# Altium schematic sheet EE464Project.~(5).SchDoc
size A; SheetNumber: 1; SheetTotal: 1
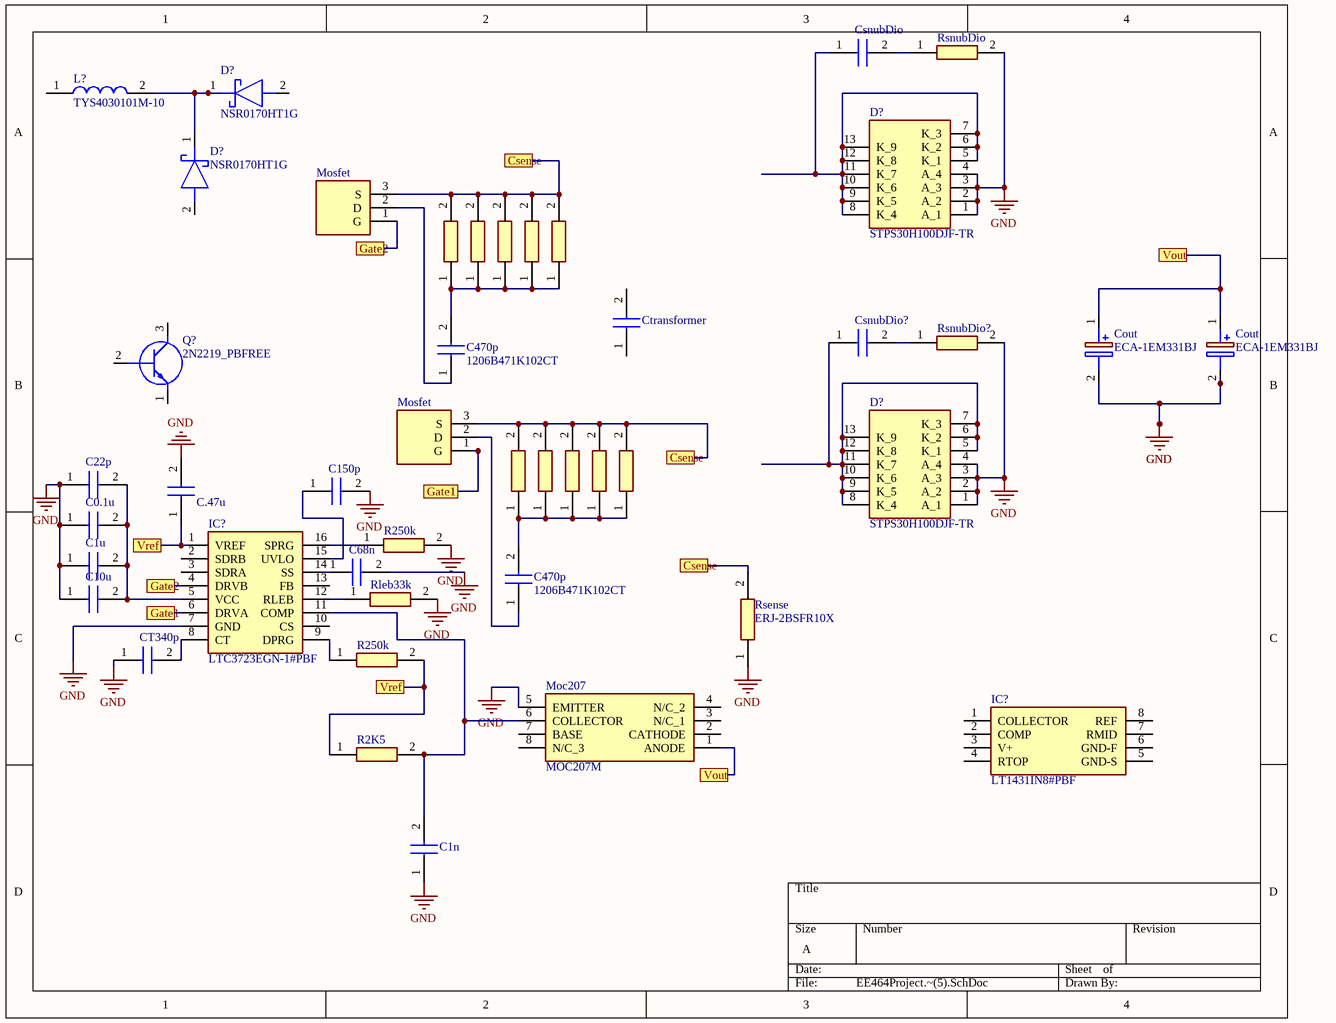
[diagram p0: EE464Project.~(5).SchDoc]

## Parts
(Parts that share a designator on the sheet are numbered #1, #2 ... from top to bottom, then left to right.)
C0.1u  06031C104K4Z2A  [CAPC1608X90N]  (value not drawn)
C1n  04025C102JAT2A  [CAPC1005X56N]  (value not drawn)
C1u  C1608X5R1H105K080AB  [CAPC1608X80N]  (value not drawn)
C10u  CL31A106MBHNNNE  [CAPC3216X180N]  (value not drawn)
C22p  06035A220JAT2A  [CAPC1608X90N]  (value not drawn)
C68n  885012206070  [CAPC1608X87N]  (value not drawn)
C150p  CL10C151JB8NNNC  [CAPC1608X90N]  (value not drawn)
C470p#1  1206B471K102CT  [CAPC3216X180N]
C470p#2  1206B471K102CT  [CAPC3216X180N]
C.47u  CGA4J1X8L1H474K125AE  [CAPC2012X145N]  (value not drawn)
Cout#1  ECA-1EM331BJ  [CAPPRD350W65D825H1250]
Cout#2  ECA-1EM331BJ  [CAPPRD350W65D825H1250]
CsnubDio  GRM1885C2A201JA01D  [CAPC1608X90N]  (value not drawn)
CsnubDio?  GRM1885C2A201JA01D  [CAPC1608X90N]  (value not drawn)
CT340p  GRM1885C2A361JA01D  [CAPC1608X90N]  (value not drawn)
Ctransformer  C1210C104KBRACAUTO  [CAPC3225X280N]  (value not drawn)
D?#1  NSR0170HT1G  [SOD2512X100N]
D?#2  NSR0170HT1G  [SOD2512X100N]
D?#3  STPS30H100DJF-TR  [STPS30H100DJFTR]
D?#4  STPS30H100DJF-TR  [STPS30H100DJFTR]
IC?#1  LTC3723EGN-1#PBF  [SOP64P601X175-16N]
IC?#2  LT1431IN8#PBF  [DIP794W53P254L1016H394Q8N]
L?  TYS4030101M-10  [INDPM4040X300N]
Moc207  MOC207M  [SOIC127P594X363-8N]
Mosfet#1  STW11NK100Z  [TO545P515X1560X2445-3P]  (value not drawn)
Mosfet#2  STW11NK100Z  [TO545P515X1560X2445-3P]  (value not drawn)
Q?  2N2219_PBFREE  [2N3440PBFREE]
R2K5  ERA-3AED2491V  [ERA3AEB101V]  (value not drawn)
R250k#1  MCT06030C2493FP500  [RESC1608X55N]  (value not drawn)
R250k#2  MCT06030C2493FP500  [RESC1608X55N]  (value not drawn)
Rleb33k  ERA-3AED333V  [ERA3AEB101V]  (value not drawn)
Rsense  ERJ-2BSFR10X  [RESC1005X40N]
RsnubDio  RC0603FR-1022RL  [RESC1608X55N]  (value not drawn)
RsnubDio?  RC0603FR-1022RL  [RESC1608X55N]  (value not drawn)
Rsnubmos  CRGH2512F221R  [RESC6432X65N]  (value not drawn)
Rsnubmos?#1  CRGH2512F221R  [RESC6432X65N]  (value not drawn)
Rsnubmos?#2  CRGH2512F221R  [RESC6432X65N]  (value not drawn)
Rsnubmos?#3  CRGH2512F221R  [RESC6432X65N]  (value not drawn)
Rsnubmos?#4  CRGH2512F221R  [RESC6432X65N]  (value not drawn)
Rsnubmos?#5  CRGH2512F221R  [RESC6432X65N]  (value not drawn)
Rsnubmos?#6  CRGH2512F221R  [RESC6432X65N]  (value not drawn)
Rsnubmos?#7  CRGH2512F221R  [RESC6432X65N]  (value not drawn)
Rsnubmos?#8  CRGH2512F221R  [RESC6432X65N]  (value not drawn)
Rsnubmos?#9  CRGH2512F221R  [RESC6432X65N]  (value not drawn)

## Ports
Csense, Gate1, Gate2, Vout, Vref

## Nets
GND: C0.1u.1 C1n.1 C1u.1 C10u.1 C22p.1 C68n.2 C150p.2 C.47u.2 Cout#1.2(-) Cout#2.2(-) CT340p.1 D?#3.1(A_1) D?#3.2(A_2) D?#3.3(A_3) D?#3.4(A_4) D?#4.1(A_1) D?#4.2(A_2) D?#4.3(A_3) D?#4.4(A_4) IC?#1.7(GND) Moc207.5(EMITTER) R250k#1.2 Rleb33k.2 Rsense.1 RsnubDio.2 RsnubDio?.2
Csense: Mosfet#1.3(S) Mosfet#2.3(S) Rsense.2 Rsnubmos.2 Rsnubmos?#1.2 Rsnubmos?#2.2 Rsnubmos?#3.2 Rsnubmos?#4.2 Rsnubmos?#5.2 Rsnubmos?#6.2 Rsnubmos?#7.2 Rsnubmos?#8.2 Rsnubmos?#9.2 ; port Csense
Gate1: IC?#1.6(DRVA) Mosfet#2.1(G) ; port Gate1
Gate2: IC?#1.4(DRVB) Mosfet#1.1(G) ; port Gate2
Vout: Cout#1.1(+) Cout#2.1(+) Moc207.1(ANODE) ; port Vout
Vref: C.47u.1 IC?#1.1(VREF) R2K5.1 R250k#2.2 ; port Vref
NetC0.1u_2: C0.1u.2 C1u.2 C10u.2 C22p.2 IC?#1.5(VCC)
NetC1n_2: C1n.2 IC?#1.11(COMP) Moc207.6(COLLECTOR) R2K5.2
NetC68n_1: C68n.1 IC?#1.14(SS)
NetC150p_1: C150p.1 IC?#1.15(UVLO)
NetC470p#1_1: C470p#1.1 Mosfet#1.2(D)
NetC470p#1_2: C470p#1.2 Rsnubmos?#1.1 Rsnubmos?#2.1 Rsnubmos?#3.1 Rsnubmos?#4.1 Rsnubmos?#5.1
NetC470p#2_1: C470p#2.1 Mosfet#2.2(D)
NetC470p#2_2: C470p#2.2 Rsnubmos.1 Rsnubmos?#6.1 Rsnubmos?#7.1 Rsnubmos?#8.1 Rsnubmos?#9.1
NetCsnubDio?_1: CsnubDio?.1 D?#4.5(K_1) D?#4.6(K_2) D?#4.7(K_3) D?#4.8(K_4) D?#4.9(K_5) D?#4.10(K_6) D?#4.11(K_7) D?#4.12(K_8) D?#4.13(K_9)
NetCsnubDio?_2: CsnubDio?.2 RsnubDio?.1
NetCsnubDio_1: CsnubDio.1 D?#3.5(K_1) D?#3.6(K_2) D?#3.7(K_3) D?#3.8(K_4) D?#3.9(K_5) D?#3.10(K_6) D?#3.11(K_7) D?#3.12(K_8) D?#3.13(K_9)
NetCsnubDio_2: CsnubDio.2 RsnubDio.1
NetCT340p_2: CT340p.2 IC?#1.8(CT)
NetD?#1_1: D?#1.1(K) D?#2.1(K) L?.2
NetIC?#1_9: IC?#1.9(DPRG) R250k#2.1
NetIC?#1_12: IC?#1.12(RLEB) Rleb33k.1
NetIC?#1_16: IC?#1.16(SPRG) R250k#1.1

Not connected (* = marked no-connect by the designer): Ctransformer 1 2; D?#1 2(A); D?#2 2(A); IC?#1 2(SDRB) 3(SDRA) 10(CS) 13(FB); IC?#2 1(COLLECTOR) 2(COMP) 3(V+) 4(RTOP) 5(GND-S) 6(GND-F) 7(RMID) 8(REF); L? 1; Moc207 2(CATHODE) 3(N/C_1) 4(N/C_2) 7(BASE) 8(N/C_3); Q? 1(E) 2(B) 3(C)

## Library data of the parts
C0.1u = 06031C104K4Z2A: Capacitor; Manufacturer_Name: AVX
C1n = 04025C102JAT2A: Capacitor; Manufacturer_Name: AVX
C1u = C1608X5R1H105K080AB: Capacitor; Manufacturer_Name: TDK
C10u = CL31A106MBHNNNE: Capacitor; Manufacturer_Name: Samsung Electro-Mechanics
C22p = 06035A220JAT2A: Capacitor; Manufacturer_Name: AVX
C68n = 885012206070: Capacitor; Manufacturer_Name: Wurth Elektronik
C150p = CL10C151JB8NNNC: Capacitor; Manufacturer_Name: Samsung Electro-Mechanics
C470p#1 C470p#2 = 1206B471K102CT: Capacitor; Manufacturer_Name: Walsin Technology Corporation
C.47u = CGA4J1X8L1H474K125AE: Capacitor; Manufacturer_Name: TDK
Cout#1 Cout#2 = ECA-1EM331BJ: Capacitor Polarised; Manufacturer_Name: Panasonic
CsnubDio CsnubDio? = GRM1885C2A201JA01D: Capacitor; Manufacturer_Name: Murata Electronics
CT340p = GRM1885C2A361JA01D: Capacitor; Manufacturer_Name: Murata Electronics
Ctransformer = C1210C104KBRACAUTO: Capacitor; Manufacturer_Name: Kemet
D?#1 D?#2 = NSR0170HT1G: Schottky Diode; Manufacturer_Name: ON Semiconductor
D?#3 D?#4 = STPS30H100DJF-TR: Schottky Diode; Manufacturer_Name: STMicroelectronics
IC?#1 = LTC3723EGN-1#PBF: Integrated Circuit; Manufacturer_Name: Linear Technology
IC?#2 = LT1431IN8#PBF: Integrated Circuit; Manufacturer_Name: Linear Technology
L? = TYS4030101M-10: Inductor; Manufacturer_Name: Laird Performance Materials
Moc207 = MOC207M: Integrated Circuit; Manufacturer_Name: ON Semiconductor
Mosfet#1 Mosfet#2 = STW11NK100Z: Integrated Circuit; Manufacturer_Name: STMicroelectronics
Q? = 2N2219_PBFREE: Transistor BJT NPN; Manufacturer_Name: Central Semiconductor; Manufacturer_Part_Number: 2N2219 PBFREE
R2K5 = ERA-3AED2491V: Resistor; Manufacturer_Name: Panasonic
R250k#1 R250k#2 = MCT06030C2493FP500: Resistor; Manufacturer_Name: Vishay
Rleb33k = ERA-3AED333V: Resistor; Manufacturer_Name: Panasonic
Rsense = ERJ-2BSFR10X: Resistor; Manufacturer_Name: Panasonic
RsnubDio RsnubDio? = RC0603FR-1022RL: Resistor; Manufacturer_Name: YAGEO (PHYCOMP)
Rsnubmos Rsnubmos?#1-Rsnubmos?#9 = CRGH2512F221R: Resistor; Manufacturer_Name: TE Connectivity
